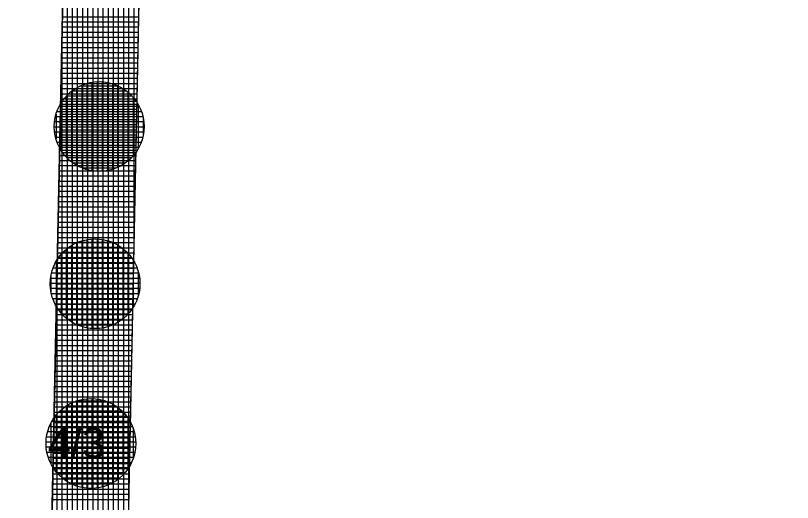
# Model space of a CAD drawing. Extents: x -566461 to -565198, y -1096301 to -1095707.
# Drawn here: x -565645.08 to -565614.79, y -1095939.73 to -1095920.77 of the extents above; entities that cross this region are included whole.
import ezdxf

# ---------------------------------------------------------------- set-up
doc = ezdxf.new("R2010")
doc.units = 0
for name, color, linetype in [('Vrstva 1', 7, 'Continuous'), ('Vrstva 40', 7, 'Continuous'), ('Vrstva 43', 7, 'Continuous'), ('Vrstva 44', 7, 'Continuous')]:
    doc.layers.add(name, color=color, linetype=linetype)

msp = doc.modelspace()

# ---------------------------------------------------------------- linework, layer by layer
at = {"layer": 'Vrstva 1'}
for p, q in [((-565645.08, -1096008.78), (-565642.52, -1095885.6)), ((-565642.11, -1096010.51), (-565639.56, -1095885.89))]:
    msp.add_line(p, q, dxfattribs=at)
at = {"layer": 'Vrstva 43'}
for p, q in [((-565642.06, -1096008.067), (-565642.06, -1095870.575)), ((-565641.86, -1095998.292), (-565641.86, -1095870.594)), ((-565641.66, -1095988.518), (-565641.66, -1095870.614)), ((-565641.46, -1095978.744), (-565641.46, -1095870.633)), ((-565641.26, -1095968.97), (-565641.26, -1095870.653)), ((-565641.06, -1095959.196), (-565641.06, -1095870.672)), ((-565640.86, -1095949.422), (-565640.86, -1095870.692)), ((-565640.66, -1095939.648), (-565640.66, -1095870.711)), ((-565640.46, -1095929.874), (-565640.46, -1095870.731)), ((-565642.26, -1096010.423), (-565642.26, -1095872.986)), ((-565642.46, -1096010.306), (-565642.46, -1095882.689)), ((-565642.66, -1096010.19), (-565642.66, -1095892.336)), ((-565642.86, -1096010.073), (-565642.86, -1095901.96)), ((-565643.06, -1096009.957), (-565643.06, -1095911.583)), ((-565643.252, -1095920.81), (-565640.275, -1095920.81)), ((-565643.26, -1096009.84), (-565643.26, -1095921.207)), ((-565643.26, -1095921.21), (-565640.283, -1095921.21)), ((-565643.256, -1095921.01), (-565640.279, -1095921.01)), ((-565643.264, -1095921.41), (-565640.287, -1095921.41)), ((-565643.273, -1095921.81), (-565640.295, -1095921.81)), ((-565643.268, -1095921.61), (-565640.291, -1095921.61)), ((-565643.277, -1095922.01), (-565640.299, -1095922.01)), ((-565643.285, -1095922.41), (-565640.307, -1095922.41)), ((-565643.281, -1095922.21), (-565640.303, -1095922.21)), ((-565643.289, -1095922.61), (-565640.311, -1095922.61)), ((-565643.297, -1095923.01), (-565640.32, -1095923.01)), ((-565643.293, -1095922.81), (-565640.315, -1095922.81)), ((-565643.302, -1095923.21), (-565640.324, -1095923.21)), ((-565643.31, -1095923.61), (-565640.332, -1095923.61)), ((-565643.306, -1095923.41), (-565640.328, -1095923.41)), ((-565643.314, -1095923.81), (-565640.336, -1095923.81)), ((-565643.322, -1095924.21), (-565640.344, -1095924.21)), ((-565643.318, -1095924.01), (-565640.34, -1095924.01)), ((-565643.327, -1095924.41), (-565640.348, -1095924.41)), ((-565643.335, -1095924.81), (-565640.356, -1095924.81)), ((-565643.331, -1095924.61), (-565640.352, -1095924.61)), ((-565643.339, -1095925.01), (-565640.36, -1095925.01)), ((-565643.347, -1095925.41), (-565640.369, -1095925.41)), ((-565643.343, -1095925.21), (-565640.365, -1095925.21)), ((-565643.352, -1095925.61), (-565640.373, -1095925.61)), ((-565643.36, -1095926.01), (-565640.381, -1095926.01)), ((-565643.356, -1095925.81), (-565640.377, -1095925.81)), ((-565643.364, -1095926.21), (-565640.385, -1095926.21)), ((-565643.372, -1095926.61), (-565640.393, -1095926.61)), ((-565643.368, -1095926.41), (-565640.389, -1095926.41)), ((-565643.376, -1095926.81), (-565640.397, -1095926.81)), ((-565643.385, -1095927.21), (-565640.405, -1095927.21)), ((-565643.381, -1095927.01), (-565640.401, -1095927.01)), ((-565643.389, -1095927.41), (-565640.41, -1095927.41)), ((-565643.397, -1095927.81), (-565640.418, -1095927.81)), ((-565643.393, -1095927.61), (-565640.414, -1095927.61)), ((-565643.401, -1095928.01), (-565640.422, -1095928.01)), ((-565643.41, -1095928.41), (-565640.43, -1095928.41)), ((-565643.406, -1095928.21), (-565640.426, -1095928.21)), ((-565643.414, -1095928.61), (-565640.434, -1095928.61)), ((-565643.422, -1095929.01), (-565640.442, -1095929.01)), ((-565643.418, -1095928.81), (-565640.438, -1095928.81)), ((-565643.426, -1095929.21), (-565640.446, -1095929.21)), ((-565643.435, -1095929.61), (-565640.455, -1095929.61)), ((-565643.43, -1095929.41), (-565640.451, -1095929.41)), ((-565643.439, -1095929.81), (-565640.459, -1095929.81)), ((-565643.447, -1095930.21), (-565640.467, -1095930.21)), ((-565643.443, -1095930.01), (-565640.463, -1095930.01)), ((-565643.451, -1095930.41), (-565640.471, -1095930.41)), ((-565643.46, -1095930.81), (-565640.479, -1095930.81)), ((-565643.46, -1096009.724), (-565643.46, -1095930.83)), ((-565643.455, -1095930.61), (-565640.475, -1095930.61)), ((-565643.464, -1095931.01), (-565640.483, -1095931.01)), ((-565643.472, -1095931.41), (-565640.491, -1095931.41)), ((-565643.468, -1095931.21), (-565640.487, -1095931.21)), ((-565643.48, -1095931.81), (-565640.5, -1095931.81)), ((-565643.476, -1095931.61), (-565640.496, -1095931.61)), ((-565643.485, -1095932.01), (-565640.504, -1095932.01)), ((-565643.493, -1095932.41), (-565640.512, -1095932.41)), ((-565643.489, -1095932.21), (-565640.508, -1095932.21)), ((-565643.497, -1095932.61), (-565640.516, -1095932.61)), ((-565643.505, -1095933.01), (-565640.524, -1095933.01)), ((-565643.501, -1095932.81), (-565640.52, -1095932.81)), ((-565643.509, -1095933.21), (-565640.528, -1095933.21)), ((-565643.518, -1095933.61), (-565640.536, -1095933.61)), ((-565643.514, -1095933.41), (-565640.532, -1095933.41)), ((-565643.522, -1095933.81), (-565640.541, -1095933.81)), ((-565643.53, -1095934.21), (-565640.549, -1095934.21)), ((-565643.526, -1095934.01), (-565640.545, -1095934.01)), ((-565643.534, -1095934.41), (-565640.553, -1095934.41)), ((-565643.543, -1095934.81), (-565640.561, -1095934.81)), ((-565643.539, -1095934.61), (-565640.557, -1095934.61)), ((-565643.547, -1095935.01), (-565640.565, -1095935.01)), ((-565643.555, -1095935.41), (-565640.573, -1095935.41)), ((-565643.551, -1095935.21), (-565640.569, -1095935.21)), ((-565643.559, -1095935.61), (-565640.577, -1095935.61)), ((-565643.568, -1095936.01), (-565640.586, -1095936.01)), ((-565643.563, -1095935.81), (-565640.581, -1095935.81)), ((-565643.572, -1095936.21), (-565640.59, -1095936.21)), ((-565643.58, -1095936.61), (-565640.598, -1095936.61)), ((-565643.576, -1095936.41), (-565640.594, -1095936.41)), ((-565643.584, -1095936.81), (-565640.602, -1095936.81)), ((-565643.593, -1095937.21), (-565640.61, -1095937.21)), ((-565643.588, -1095937.01), (-565640.606, -1095937.01)), ((-565643.597, -1095937.41), (-565640.614, -1095937.41)), ((-565643.605, -1095937.81), (-565640.622, -1095937.81)), ((-565643.601, -1095937.61), (-565640.618, -1095937.61)), ((-565643.609, -1095938.01), (-565640.626, -1095938.01)), ((-565643.618, -1095938.41), (-565640.635, -1095938.41)), ((-565643.613, -1095938.21), (-565640.631, -1095938.21)), ((-565643.622, -1095938.61), (-565640.639, -1095938.61)), ((-565643.63, -1095939.01), (-565640.647, -1095939.01)), ((-565643.626, -1095938.81), (-565640.643, -1095938.81)), ((-565643.634, -1095939.21), (-565640.651, -1095939.21)), ((-565643.642, -1095939.61), (-565640.659, -1095939.61)), ((-565643.638, -1095939.41), (-565640.655, -1095939.41))]:
    msp.add_line(p, q, dxfattribs=at)
msp.add_lwpolyline([(-565639.56, -1095885.89), (-565630.78, -1095886.75), (-565609.49, -1095886.27), (-565595.88, -1095884.74), (-565585.92, -1095883.62), (-565568.01, -1095880.69), (-565521.32, -1095878.21), (-565519.36, -1095863.08), (-565522.03, -1095863.23), (-565569.62, -1095865.76), (-565587.97, -1095868.76), (-565610.5, -1095871.29), (-565630.22, -1095871.73), (-565642.21, -1095870.56), (-565642.52, -1095885.6), (-565645.08, -1096008.78), (-565642.11, -1096010.51)], close=True, dxfattribs=at)
at = {"layer": 'Vrstva 44'}
for p, q in [((-565642.7, -1095923.579), (-565642.7, -1095926.6)), ((-565641.072, -1095923.51), (-565642.569, -1095923.51)), ((-565642.5, -1095923.479), (-565642.5, -1095926.701)), ((-565642.3, -1095923.408), (-565642.3, -1095926.772)), ((-565642.1, -1095923.364), (-565642.1, -1095926.816)), ((-565641.9, -1095923.344), (-565641.9, -1095926.837)), ((-565641.7, -1095923.346), (-565641.7, -1095926.836)), ((-565641.5, -1095923.371), (-565641.5, -1095926.809)), ((-565641.3, -1095923.419), (-565641.3, -1095926.759)), ((-565641.1, -1095923.497), (-565641.1, -1095926.683)), ((-565640.9, -1095923.603), (-565640.9, -1095926.578)), ((-565640.53, -1095923.91), (-565643.111, -1095923.91)), ((-565643.1, -1095923.899), (-565643.1, -1095926.281)), ((-565642.9, -1095923.714), (-565642.9, -1095926.467)), ((-565640.746, -1095923.71), (-565642.895, -1095923.71)), ((-565640.7, -1095923.746), (-565640.7, -1095926.432)), ((-565643.3, -1095924.159), (-565643.3, -1095926.02)), ((-565640.371, -1095924.11), (-565643.268, -1095924.11)), ((-565640.5, -1095923.943), (-565640.5, -1095926.237)), ((-565640.3, -1095924.225), (-565640.3, -1095925.954)), ((-565640.171, -1095924.51), (-565643.471, -1095924.51)), ((-565640.256, -1095924.31), (-565643.385, -1095924.31)), ((-565640.112, -1095924.71), (-565643.527, -1095924.71)), ((-565643.5, -1095924.607), (-565643.5, -1095925.573)), ((-565640.1, -1095924.778), (-565640.1, -1095925.406)), ((-565640.072, -1095925.11), (-565643.568, -1095925.11)), ((-565640.081, -1095924.91), (-565643.559, -1095924.91)), ((-565640.086, -1095925.31), (-565643.555, -1095925.31)), ((-565640.122, -1095925.51), (-565643.518, -1095925.51)), ((-565640.184, -1095925.71), (-565643.455, -1095925.71)), ((-565640.276, -1095925.91), (-565643.364, -1095925.91)), ((-565640.4, -1095926.11), (-565643.241, -1095926.11)), ((-565640.568, -1095926.31), (-565643.072, -1095926.31)), ((-565640.799, -1095926.51), (-565642.839, -1095926.51)), ((-565641.163, -1095926.71), (-565642.481, -1095926.71)), ((-565642.7, -1095929.617), (-565642.7, -1095932.803)), ((-565641.295, -1095929.6), (-565642.661, -1095929.6)), ((-565642.5, -1095929.541), (-565642.5, -1095932.88)), ((-565642.3, -1095929.49), (-565642.3, -1095932.929)), ((-565642.1, -1095929.465), (-565642.1, -1095932.954)), ((-565641.9, -1095929.464), (-565641.9, -1095932.957)), ((-565641.7, -1095929.485), (-565641.7, -1095932.937)), ((-565641.5, -1095929.529), (-565641.5, -1095932.892)), ((-565641.3, -1095929.598), (-565641.3, -1095932.82)), ((-565643.1, -1095929.868), (-565643.1, -1095932.553)), ((-565640.947, -1095929.8), (-565643.014, -1095929.8)), ((-565642.9, -1095929.722), (-565642.9, -1095932.697)), ((-565641.1, -1095929.7), (-565641.1, -1095932.721)), ((-565640.9, -1095929.835), (-565640.9, -1095932.585)), ((-565640.552, -1095930.2), (-565643.408, -1095930.2)), ((-565643.3, -1095930.062), (-565643.3, -1095932.358)), ((-565640.718, -1095930), (-565643.242, -1095930)), ((-565640.7, -1095930.02), (-565640.7, -1095932.402)), ((-565640.5, -1095930.28), (-565640.5, -1095932.142)), ((-565640.43, -1095930.4), (-565643.529, -1095930.4)), ((-565643.5, -1095930.345), (-565643.5, -1095932.077)), ((-565643.7, -1095930.897), (-565643.7, -1095931.522)), ((-565640.28, -1095930.8), (-565643.681, -1095930.8)), ((-565640.342, -1095930.6), (-565643.619, -1095930.6)), ((-565640.3, -1095930.727), (-565640.3, -1095931.695)), ((-565640.231, -1095931.2), (-565643.728, -1095931.2)), ((-565640.243, -1095931), (-565643.716, -1095931)), ((-565640.242, -1095931.4), (-565643.718, -1095931.4)), ((-565640.276, -1095931.6), (-565643.685, -1095931.6)), ((-565640.333, -1095931.8), (-565643.626, -1095931.8)), ((-565640.42, -1095932), (-565643.539, -1095932)), ((-565640.539, -1095932.2), (-565643.422, -1095932.2)), ((-565640.698, -1095932.4), (-565643.26, -1095932.4)), ((-565640.918, -1095932.6), (-565643.041, -1095932.6)), ((-565641.252, -1095932.8), (-565642.706, -1095932.8)), ((-565642.5, -1095935.719), (-565642.5, -1095939.142)), ((-565642.3, -1095935.688), (-565642.3, -1095939.171)), ((-565642.1, -1095935.681), (-565642.1, -1095939.178)), ((-565641.9, -1095935.698), (-565641.9, -1095939.162)), ((-565641.7, -1095935.738), (-565641.7, -1095939.123)), ((-565641.161, -1095935.98), (-565643.117, -1095935.98)), ((-565643.1, -1095935.968), (-565643.1, -1095938.893)), ((-565642.9, -1095935.855), (-565642.9, -1095939.005)), ((-565641.563, -1095935.78), (-565642.718, -1095935.78)), ((-565642.7, -1095935.774), (-565642.7, -1095939.086)), ((-565641.5, -1095935.803), (-565641.5, -1095939.057)), ((-565641.3, -1095935.896), (-565641.3, -1095938.963)), ((-565641.1, -1095936.025), (-565641.1, -1095938.837)), ((-565643.5, -1095936.332), (-565643.5, -1095938.529)), ((-565640.916, -1095936.18), (-565643.363, -1095936.18)), ((-565643.3, -1095936.122), (-565643.3, -1095938.738)), ((-565640.9, -1095936.196), (-565640.9, -1095938.662)), ((-565643.7, -1095936.641), (-565643.7, -1095938.219)), ((-565640.611, -1095936.58), (-565643.668, -1095936.58)), ((-565640.742, -1095936.38), (-565643.539, -1095936.38)), ((-565640.7, -1095936.436), (-565640.7, -1095938.421)), ((-565640.517, -1095936.78), (-565643.763, -1095936.78)), ((-565640.5, -1095936.825), (-565640.5, -1095938.041)), ((-565640.409, -1095937.18), (-565643.871, -1095937.18)), ((-565640.451, -1095936.98), (-565643.83, -1095936.98)), ((-565640.391, -1095937.38), (-565643.888, -1095937.38)), ((-565640.398, -1095937.58), (-565643.882, -1095937.58)), ((-565640.427, -1095937.78), (-565643.853, -1095937.78)), ((-565640.481, -1095937.98), (-565643.801, -1095937.98)), ((-565640.56, -1095938.18), (-565643.72, -1095938.18)), ((-565640.672, -1095938.38), (-565643.607, -1095938.38)), ((-565640.823, -1095938.58), (-565643.458, -1095938.58)), ((-565641.03, -1095938.78), (-565643.252, -1095938.78)), ((-565641.331, -1095938.98), (-565642.952, -1095938.98))]:
    msp.add_line(p, q, dxfattribs=at)
for centre in [(-565641.82, -1095925.09), (-565641.98, -1095931.21), (-565642.14, -1095937.43)]:
    msp.add_circle(centre, 1.75, dxfattribs=at)

# ---------------------------------------------------------------- texts
at = {"layer": 'Vrstva 40'}
msp.add_text('4/3', height=1.2, dxfattribs=at).set_placement((-565643.82, -1095938.01))

doc.saveas('drawing.dxf')
